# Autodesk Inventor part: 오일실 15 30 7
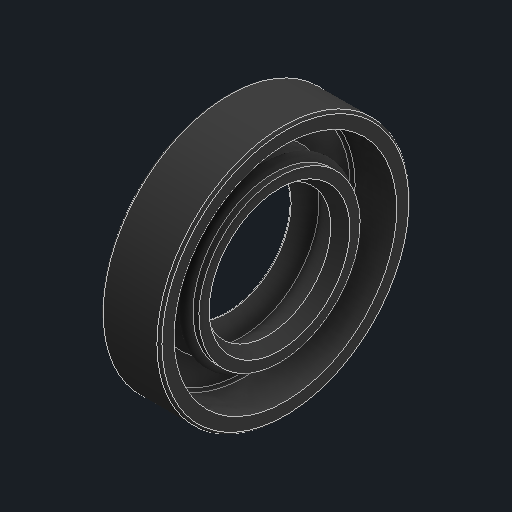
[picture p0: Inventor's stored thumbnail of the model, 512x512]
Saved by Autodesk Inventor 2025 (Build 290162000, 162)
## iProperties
Created: 2025-08
Part Number: 오일실 15 30 7
Material: 고무
Description: 오일-실
Document SubType Name: Modeling
Designer: infra14
Density: 0.93 g/cm^3
Appearance: 기본값
Author: jhkim
Sending System: Autodesk Inventor 2026
Preprocessor: ST-DEVELOPER v20.1
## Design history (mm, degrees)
feature "Solid1"
node "솔리드1"
